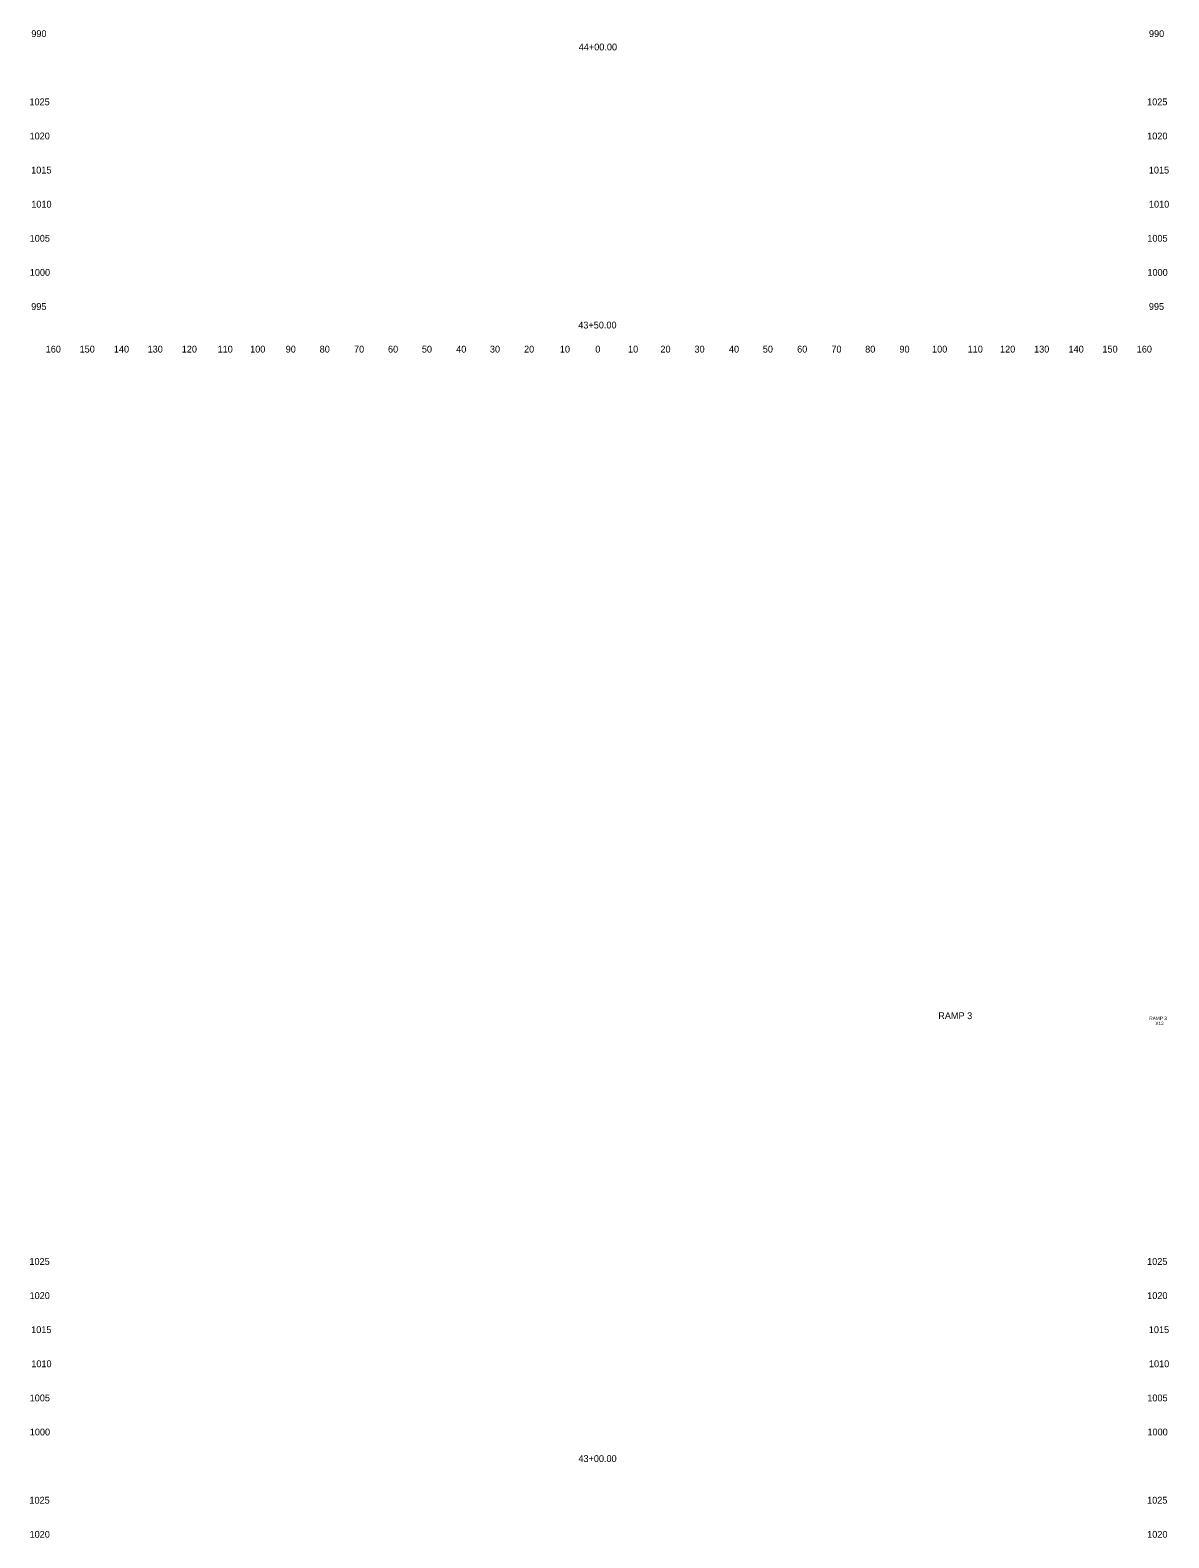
# Model space of a CAD drawing. Extents: x 4994 to 5843, y 4997 to 8804.
# Drawn here: x 5508.5 to 5842.5, y 5450 to 5892 of the extents above; entities that cross this region are included whole.
import ezdxf

# ---------------------------------------------------------------- set-up
doc = ezdxf.new("R2010")
doc.units = 0
for name, color, linetype in [('RD_SHT_ID', 7, 'Continuous'), ('RD_XS_TX_Offset', 7, 'Continuous'), ('RD_XS_TX_Station', 7, 'Continuous')]:
    doc.layers.add(name, color=color, linetype=linetype)

msp = doc.modelspace()

# ---------------------------------------------------------------- texts
at = {"layer": 'RD_SHT_ID'}
for s, height, p in [('RAMP 3', 2, (5774.89, 5602.06)), ('RAMP 3', 1, (5836.78, 5601.8)), ('X12', 1, (5838.57, 5600.3))]:
    msp.add_text(s, height=height, dxfattribs=at).set_placement(p)
at = {"layer": 'RD_XS_TX_Offset'}
for s, p in [('990', (5508.89, 5890)), ('990', (5836.69, 5890)), ('1025', (5508.34, 5870)), ('1025', (5836.14, 5870)), ('1020', (5508.37, 5860)), ('1020', (5836.17, 5860)), ('1015', (5508.85, 5850)), ('1015', (5836.65, 5850)), ('1010', (5508.88, 5840)), ('1010', (5836.68, 5840)), ('1005', (5508.4, 5830)), ('1005', (5836.2, 5830)), ('1000', (5508.44, 5820)), ('1000', (5836.24, 5820)), ('995', (5508.86, 5810)), ('995', (5836.66, 5810)), ('160', (5513.1, 5797.5)), ('150', (5523.04, 5797.5)), ('140', (5533.1, 5797.5)), ('130', (5542.99, 5797.5)), ('120', (5553.01, 5797.5)), ('110', (5563.51, 5797.5)), ('100', (5573.07, 5797.5)), ('90', (5583.5, 5797.5)), ('80', (5593.46, 5797.5)), ('70', (5603.54, 5797.5)), ('60', (5613.5, 5797.5)), ('50', (5623.43, 5797.5)), ('40', (5633.5, 5797.5)), ('30', (5643.39, 5797.5)), ('20', (5653.4, 5797.5)), ('10', (5663.91, 5797.5)), ('0', (5674.3, 5797.5)), ('0', (5674.3, 5797.5)), ('10', (5683.91, 5797.5)), ('20', (5693.4, 5797.5)), ('30', (5703.39, 5797.5)), ('40', (5713.5, 5797.5)), ('50', (5723.43, 5797.5)), ('60', (5733.5, 5797.5)), ('70', (5743.54, 5797.5)), ('80', (5753.46, 5797.5)), ('90', (5763.5, 5797.5)), ('100', (5773.07, 5797.5)), ('110', (5783.51, 5797.5)), ('120', (5793.01, 5797.5)), ('130', (5802.99, 5797.5)), ('140', (5813.1, 5797.5)), ('150', (5823.04, 5797.5)), ('160', (5833.1, 5797.5)), ('1025', (5508.34, 5530)), ('1025', (5836.14, 5530)), ('1020', (5508.37, 5520)), ('1020', (5836.17, 5520)), ('1015', (5508.85, 5510)), ('1015', (5836.65, 5510)), ('1010', (5508.88, 5500)), ('1010', (5836.68, 5500)), ('1005', (5508.4, 5490)), ('1005', (5836.2, 5490)), ('1000', (5508.44, 5480)), ('1000', (5836.24, 5480)), ('1025', (5508.34, 5460)), ('1025', (5836.14, 5460)), ('1020', (5508.37, 5450)), ('1020', (5836.17, 5450))]:
    msp.add_text(s, height=2, dxfattribs=at).set_placement(p)
at = {"layer": 'RD_XS_TX_Station'}
for s, p in [('44+00.00', (5669.45, 5886.09)), ('43+50.00', (5669.31, 5804.56)), ('43+00.00', (5669.34, 5472.2))]:
    msp.add_text(s, height=2, dxfattribs=at).set_placement(p)

doc.saveas('drawing.dxf')
